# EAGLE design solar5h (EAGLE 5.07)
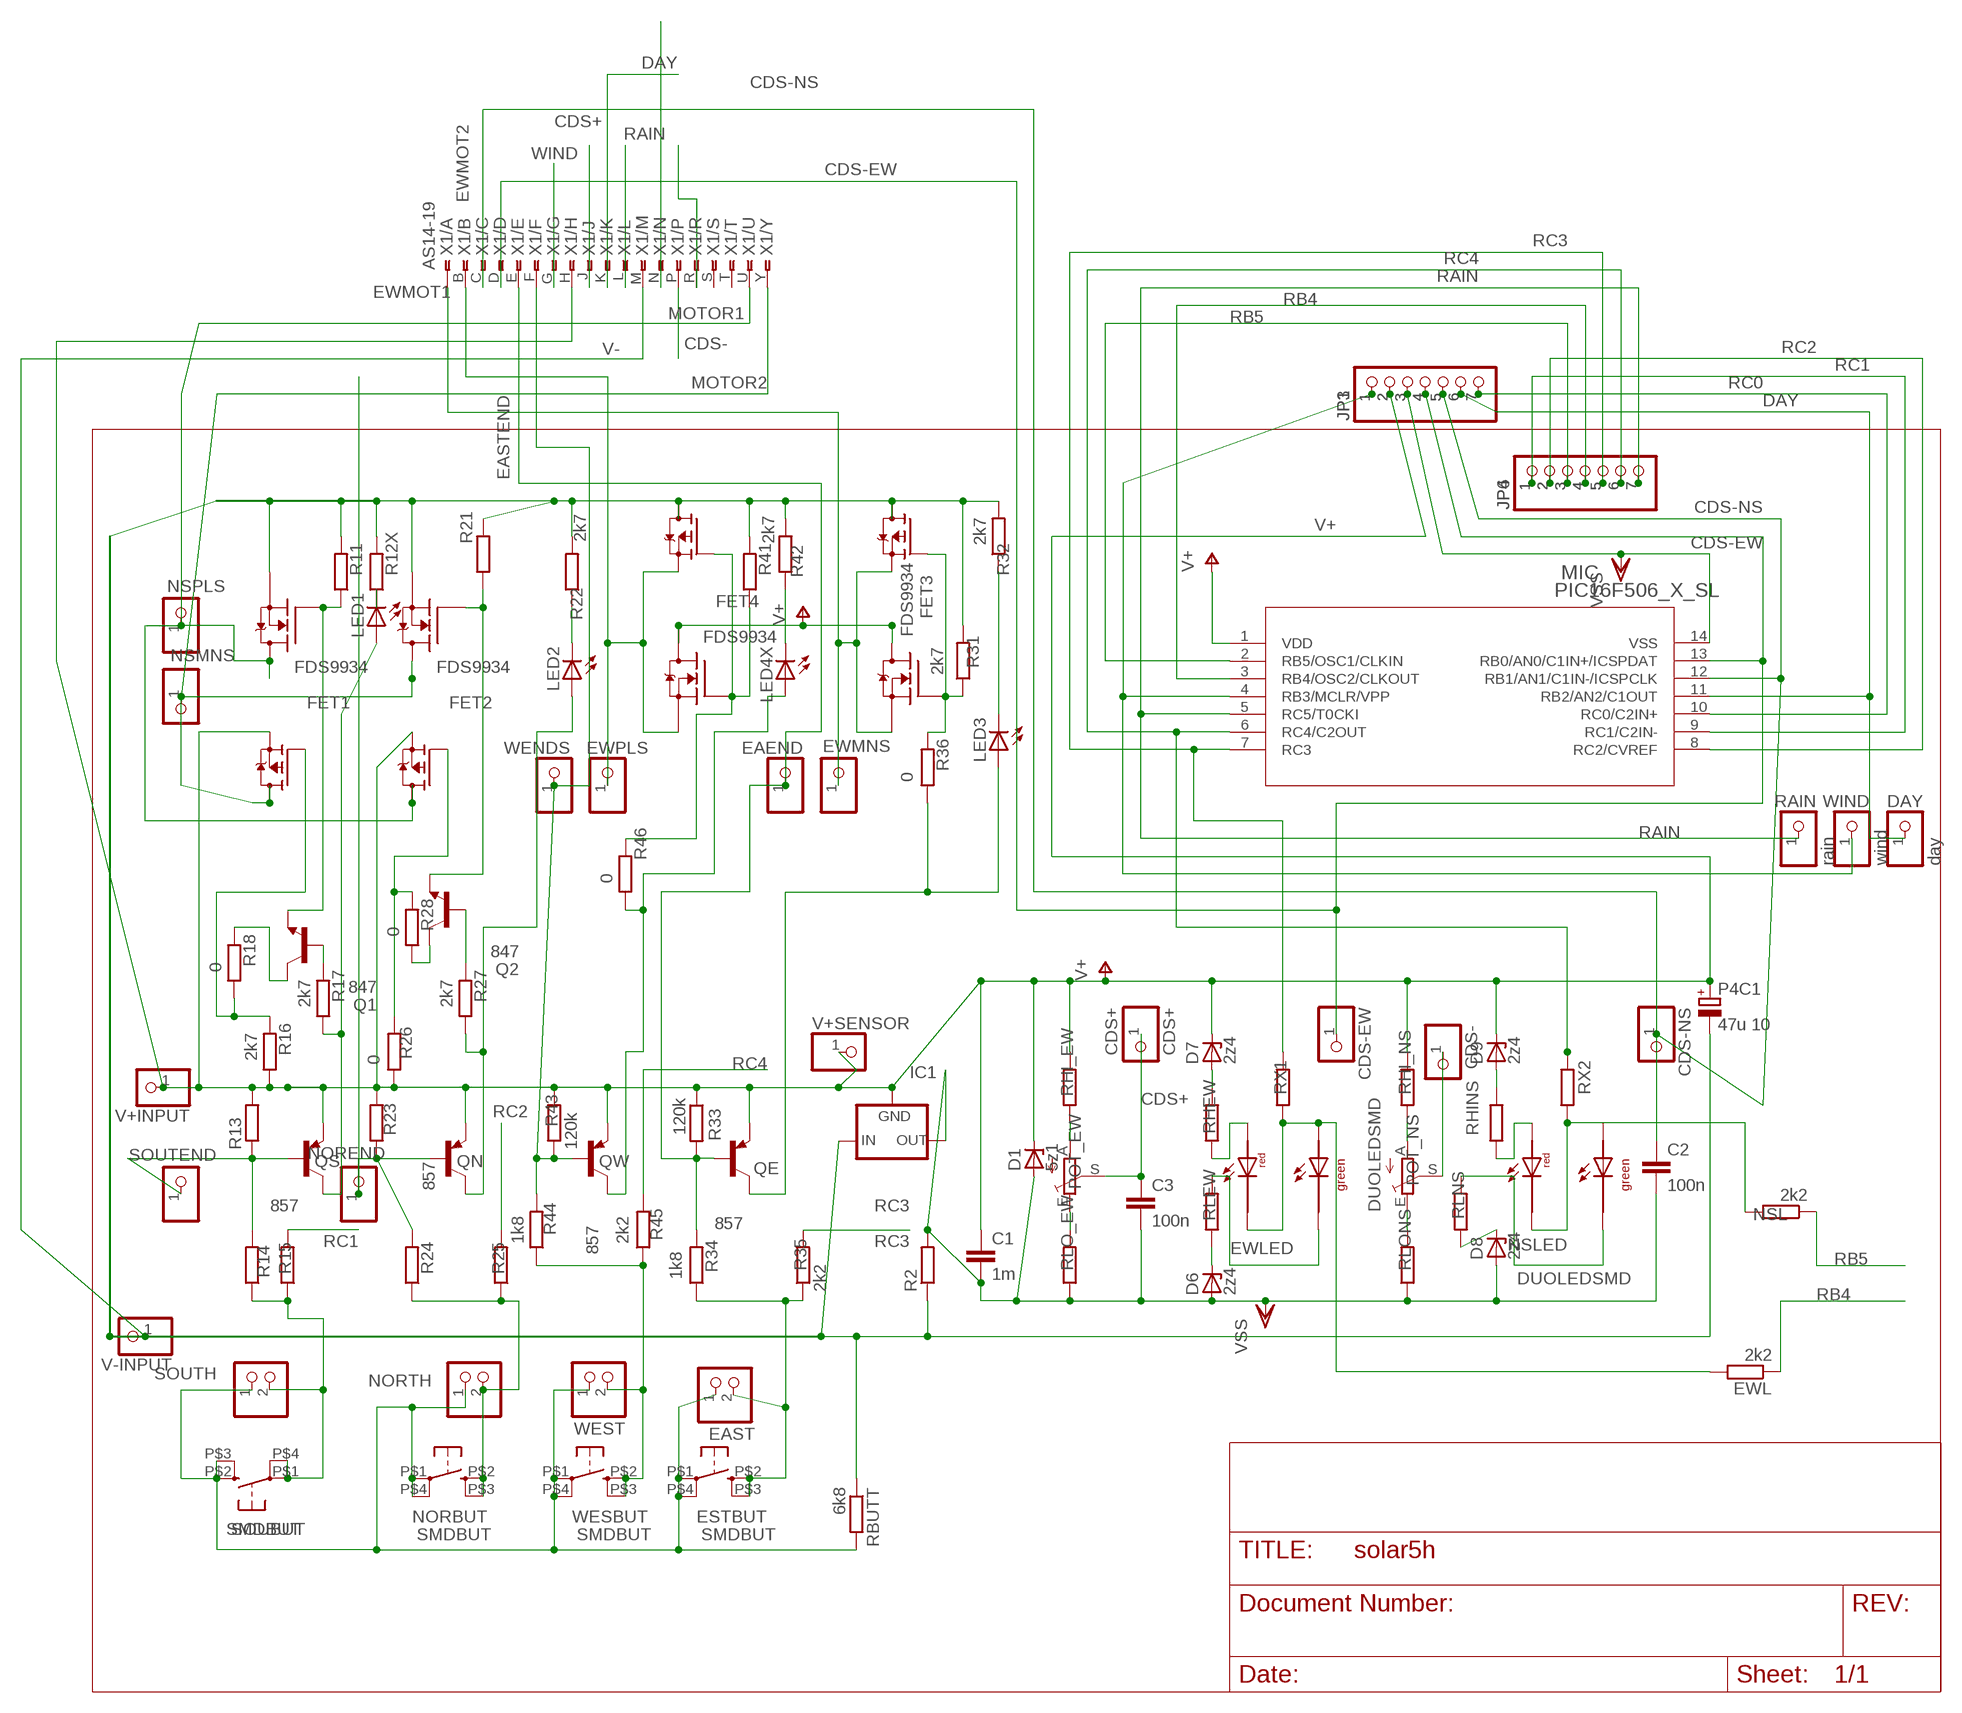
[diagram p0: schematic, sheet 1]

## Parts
C1  1m  C-EUC1206  [C1206]
C2  100n  C-EUC1206  [C1206]
C3  100n  C-EUC1206  [C1206]
CDS+  CDS+  PINHD-1X1INCH  [1X01]
CDS-  PINHD-1X1INCH  [1X01]
CDS-EW  PINHD-1X1INCH  [1X01]
CDS-NS  PINHD-1X1INCH  [1X01]
D1  5z1  ZENER-DIODESOD80C  [SOD80C]
D6  2z4  ZENER-DIODESOD80C  [SOD80C]
D7  2z4  ZENER-DIODESOD80C  [SOD80C]
D8  2z4  ZENER-DIODESOD80C  [SOD80C]
D9  2z4  ZENER-DIODESOD80C  [SOD80C]
DAY  day  PINHD-1X1INCH  [1X01]
EAEND  PINHD-1X1INCH  [1X01]
EAST  PINHD-1X2STR  [1X02]
ESTBUT  SMDBUT  [SMD10/5]
EWL  2k2  R-EU_R0805  [R0805]
EWLED  DUOLEDSMD  [DUOLEDSMD]
EWMNS  PINHD-1X10MM6  [1X01M]
EWPLS  PINHD-1X10MM6  [1X01M]
FET1  FDS9934  [SO-8]
FET2  FDS9934  [SO-8]
FET3  FDS9934  [SO-8]
FET4  FDS9934  [SO-8]
IC1  79LXX  [79LXX]
JP1  PINHD-1X7  [1X07]
JP3  PINHD-1X7  [1X07]
JP4  PINHD-1X7  [1X07]
JP6  PINHD-1X7  [1X07]
LED1  LEDCHIPLED_1206  [CHIPLED_1206]
LED2  LEDCHIPLED_1206  [CHIPLED_1206]
LED3  LEDCHIPLED_1206  [CHIPLED_1206]
LED4X  LEDCHIPLED_1206  [CHIPLED_1206]
MIC  PIC16F506_X_SL  [SOIC14_N_MC]
NORBUT  SMDBUT  [SMD10/5]
NOREND  PINHD-1X1INCH  [1X01]
NORTH  PINHD-1X2STR  [1X02]
NSL  2k2  R-EU_R0805  [R0805]
NSLED  DUOLEDSMD  [DUOLEDSMD]
NSMNS  PINHD-1X1INCH  [1X01]
NSPLS  PINHD-1X10MM6  [1X01M]
P4C1  47u 10  CPOL-EUE5-8.5  [E5-8,5]
POT_EW  TRIM_EU-CA6V  [CA6V]
POT_NS  TRIM_EU-CA6V  [CA6V]
Q1  847  BC847ASMD  [SOT23]
Q2  847  BC847ASMD  [SOT23]
QE  857  BC327SMD  [SOT23-BEC]
QN  857  BC327SMD  [SOT23-BEC]
QS  857  BC327SMD  [SOT23-BEC]
QW  857  BC327SMD  [SOT23-BEC]
R2  R-EU_R0805  [R0805]
R11  R-EU_R1206  [R1206]
R12X  R-EU_R0805  [R0805]
R13  R-EU_R0805  [R0805]
R14  R-EU_R1206  [R1206]
R15  R-EU_R0805  [R0805]
R16  2k7  R-EU_R0805  [R0805]
R17  2k7  R-EU_R0805  [R0805]
R18  0  R-EU_R0805  [R0805]
R21  R-EU_R0805  [R0805]
R22  2k7  R-EU_R0805  [R0805]
R23  R-EU_R0805  [R0805]
R24  R-EU_R1206  [R1206]
R25  R-EU_R0805  [R0805]
R26  0  R-EU_R0805  [R0805]
R27  2k7  R-EU_R0805  [R0805]
R28  0  R-EU_R0805  [R0805]
R31  2k7  R-EU_R0805  [R0805]
R32  2k7  R-EU_R0805  [R0805]
R33  120k  R-EU_R0805  [R0805]
R34  1k8  R-EU_R0805  [R0805]
R35  2k2  R-EU_R0805  [R0805]
R36  0  R-EU_R0805  [R0805]
R41  R-EU_R0805  [R0805]
R42  2k7  R-EU_R0805  [R0805]
R43  120k  R-EU_R0805  [R0805]
R44  1k8  R-EU_R0805  [R0805]
R45  2k2  R-EU_R0805  [R0805]
R46  0  R-EU_R0805  [R0805]
RAIN  rain  PINHD-1X1INCH  [1X01]
RBUTT  6k8  R-EU_R0805  [R0805]
RHEW  R-EU_R1206  [R1206]
RHI_EW  R-EU_R1206  [R1206]
RHI_NS  R-EU_R1206  [R1206]
RHINS  R-EU_R1206  [R1206]
RLEW  R-EU_R1206  [R1206]
RLNS  R-EU_R1206  [R1206]
RLO_EW  R-EU_R1206  [R1206]
RLONS  R-EU_R0805  [R0805]
RX1  R-EU_R1206  [R1206]
RX2  R-EU_R0805  [R0805]
SOUBUT  SMDBUT  [SMD10/5]
SOUTEND  PINHD-1X1INCH  [1X01]
SOUTH  PINHD-1X2STR  [1X02]
V+INPUT  PINHD-1X1INCH  [1X01]
V+SENSOR  PINHD-1X10MM6  [1X01M]
V-INPUT  PINHD-1X10MM6  [1X01M]
WENDS  PINHD-1X1INCH  [1X01]
WESBUT  SMDBUT  [SMD10/5]
WEST  PINHD-1X2STR  [1X02]
WIND  wind  PINHD-1X1INCH  [1X01]
X1  AS14-19  AS14-19OLIVE  [Y28M-19TK]

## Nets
CDS+: C3.1 CDS+.1 POT_EW.S X1.J
CDS-: CDS-.1 POT_NS.S X1.P
CDS-EW: CDS-EW.1 JP1.4 JP3.4 MIC.13(RB0/AN0/C1IN+/ICSPDAT) X1.D
CDS-NS: C2.1 CDS-NS.1 JP1.5 JP3.5 MIC.12(RB1/AN1/C1IN-/ICSPCLK) X1.C
DAY: DAY.1 JP1.6 JP3.6 MIC.11(RB2/AN2/C1OUT) X1.K
EASTEND: EAEND.1 QE.B R33.2 R34.2 X1.E
EWMOT1: EWMNS.1 FET3.1(Q1S) FET3.3(Q2S) X1.A
EWMOT2: EWPLS.1 FET4.1(Q1S) FET4.3(Q2S) X1.B
F1NG: FET1.2(Q1G) Q1.2(E) R11.1
F1PG: FET1.4(Q2G) R16.2 R18.1
F2NG: FET2.2(Q1G) Q2.2(E) R21.1
F2PG: FET2.4(Q2G) R26.2 R28.2
MOTOR1: FET1.7(Q1D2) FET1.8(Q1D1) FET2.5(Q2D2) FET2.6(Q2D) NSPLS.1 X1.U
MOTOR2: FET1.5(Q2D2) FET1.6(Q2D) FET2.7(Q1D2) FET2.8(Q1D1) NSMNS.1 X1.Y
N$1: POT_NS.E RLONS.2
N$2: LED1.A QS.C R17.1
N$3: LED2.A QN.C R27.1
N$5: LED1.C R12X.1
N$6: EWL.2 EWLED.AGRN EWLED.CRED RX1.1
N$8: LED2.C R22.1
N$9: R14.1 R15.1 SOUBUT.P$1(P) SOUBUT.P$4(P1) SOUTH.2
N$10: LED4X.A QW.C R46.1
N$11: EAST.2 ESTBUT.P$2(S) ESTBUT.P$3(S1) R34.1 R35.1
N$12: Q2.3(C) R28.1
N$14: D7.A RHEW.2
N$15: LED4X.C R42.1
N$17: NORBUT.P$2(S) NORBUT.P$3(S1) NORTH.2 R24.1 R25.1
N$18: POT_NS.A RHI_NS.1
N$19: Q1.1(B) R17.2
N$20: Q1.3(C) R18.2
N$21: POT_EW.E RLO_EW.2
N$22: POT_EW.A RHI_EW.1
N$23: Q2.1(B) R27.2
N$25: EWLED.ARED RHEW.1
N$27: D6.C RLEW.1
N$28: EWLED.CGRN RLEW.2
N$29: EAST.1 ESTBUT.P$1(P) ESTBUT.P$4(P1) NORBUT.P$1(P) NORBUT.P$4(P1) NORTH.1 RBUTT.2 SOUBUT.P$2(S) SOUBUT.P$3(S1) SOUTH.1 WESBUT.P$1(P) WESBUT.P$4(P1) WEST.1
N$30: NSL.2 NSLED.AGRN NSLED.CRED RX2.1
N$37: LED3.A QE.C R36.1
N$39: R44.1 R45.1 WESBUT.P$2(S) WESBUT.P$3(S1) WEST.2
N$41: D9.A RHINS.2
N$42: NSLED.ARED RHINS.1
N$43: D8.C RLNS.1
N$44: NSLED.CGRN RLNS.2
N$54: FET4.2(Q1G) FET4.4(Q2G) R41.1 R46.2
N$55: FET3.2(Q1G) FET3.4(Q2G) R31.1 R36.2
N$56: LED3.C R32.1
NOREND: NOREND.1 QN.B R23.1 R24.2 X1.N
RAIN: JP4.7 JP6.7 MIC.5(RC5/T0CKI) RAIN.1 X1.L
RB4: EWL.1 JP4.4 JP6.4 MIC.3(RB4/OSC2/CLKOUT)
RB5: JP4.3 JP6.3 MIC.2(RB5/OSC1/CLKIN) NSL.1
RC0: JP1.7 JP3.7 MIC.10(RC0/C2IN+)
RC1: JP4.1 JP6.1 MIC.9(RC1/C2IN-) R15.2
RC2: JP4.2 JP6.2 MIC.8(RC2/CVREF) R25.2
RC3: JP4.5 JP6.5 MIC.7(RC3) R35.2 RX1.2
RC4: JP4.6 JP6.6 MIC.6(RC4/C2OUT) R45.2 RX2.2
SOU_END: QS.B R13.1 R14.2 SOUTEND.1 X1.R
V+: C1.1 D1.C D7.C D9.C FET1.3(Q2S) FET2.3(Q2S) FET3.7(Q1D2) FET3.8(Q1D1) FET4.7(Q1D2) FET4.8(Q1D1) IC1.GND JP1.2 JP3.2 MIC.1(VDD) P4C1.+ QE.E QN.E QS.E QW.E R13.2 R16.1 R23.2 R26.1 R33.1 R43.2 RHI_EW.2 RHI_NS.2 V+INPUT.1 V+SENSOR.1 X1.H
V-: FET1.1(Q1S) FET2.1(Q1S) FET3.5(Q2D2) FET3.6(Q2D) FET4.5(Q2D2) FET4.6(Q2D) IC1.IN P4C1.- R2.1 R11.2 R12X.2 R21.2 R22.2 R31.2 R32.2 R41.2 R42.2 RBUTT.1 V-INPUT.1 X1.M
VSS: C1.2 C2.2 C3.2 D1.A D6.A D8.A IC1.OUT JP1.3 JP3.3 MIC.14(VSS) R2.2 RLO_EW.1 RLONS.1
WESTEND: QW.B R43.1 R44.2 WENDS.1 X1.F
WIND: JP1.1 JP3.1 MIC.4(RB3/MCLR/VPP) WIND.1 X1.G
Unconnected: X1.S X1.T

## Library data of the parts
C1-C3 = rcl-2:C-EU: CAPACITOR, European symbol
CDS+ CDS- CDS-EW CDS-NS DAY EAEND EWMNS EWPLS NOREND NSMNS NSPLS RAIN SOUTEND V+INPUT V+SENSOR V-INPUT WENDS WIND = pinhead(2):PINHD-1X1: PIN HEADER
D1 D6-D9 = diode-1:ZENER-DIODE: Z-Diode
EAST NORTH SOUTH WEST = pinhead:PINHD-1X2: PIN HEADER
ESTBUT NORBUT SOUBUT WESBUT = switch-omron:SMDBUT
EWL NSL R2 R11 R12X R13-R18 R21-R28 R31-R36 R41-R46 RBUTT RHEW RHI_EW RHI_NS RHINS RLEW RLNS RLO_EW RLONS RX1 RX2 = rcl-2:R-EU_: RESISTOR, European symbol
EWLED NSLED = led:DUOLEDSMD
FET1-FET4 = transistor-fet:FDS9934
IC1 = v-reg:79LXX: VOLTAGE REGULATOR
JP1 JP3 JP4 JP6 = pinhead:PINHD-1X7: PIN HEADER
LED1-LED3 LED4X = led:LED: LED
MIC = pic16f506mc:PIC16F506_X_SL
P4C1 = rcl:CPOL-EU: POLARIZED CAPACITOR, European symbol
POT_EW POT_NS = pot:TRIM_EU-: POTENTIOMETER
Q1 Q2 = transistor-npn:BC847*: NPN Transistor
QE QN QS QW = transistor-pnp:BC327*: PNP Transistror
X1 = con-deutsch:AS14-19: DEUTSCH Connector

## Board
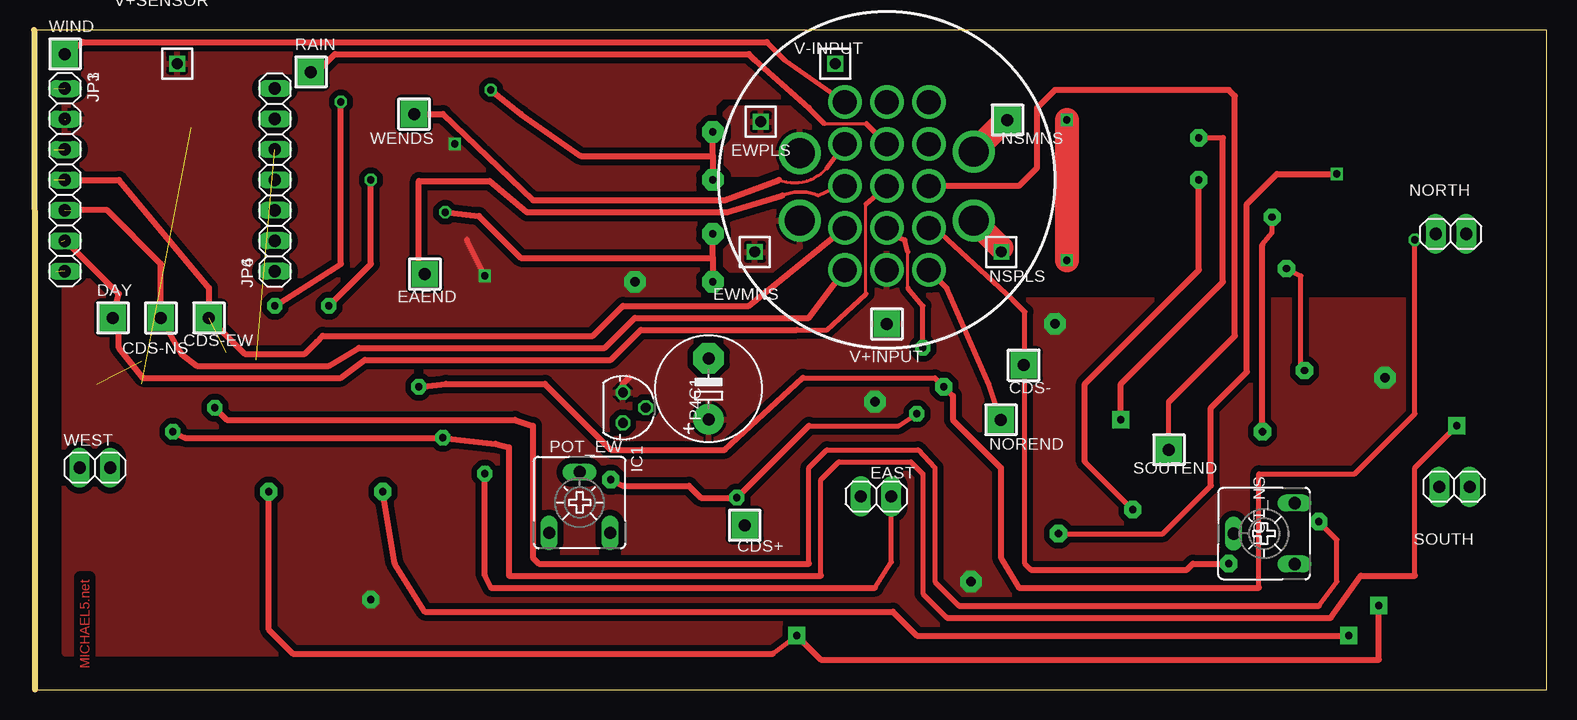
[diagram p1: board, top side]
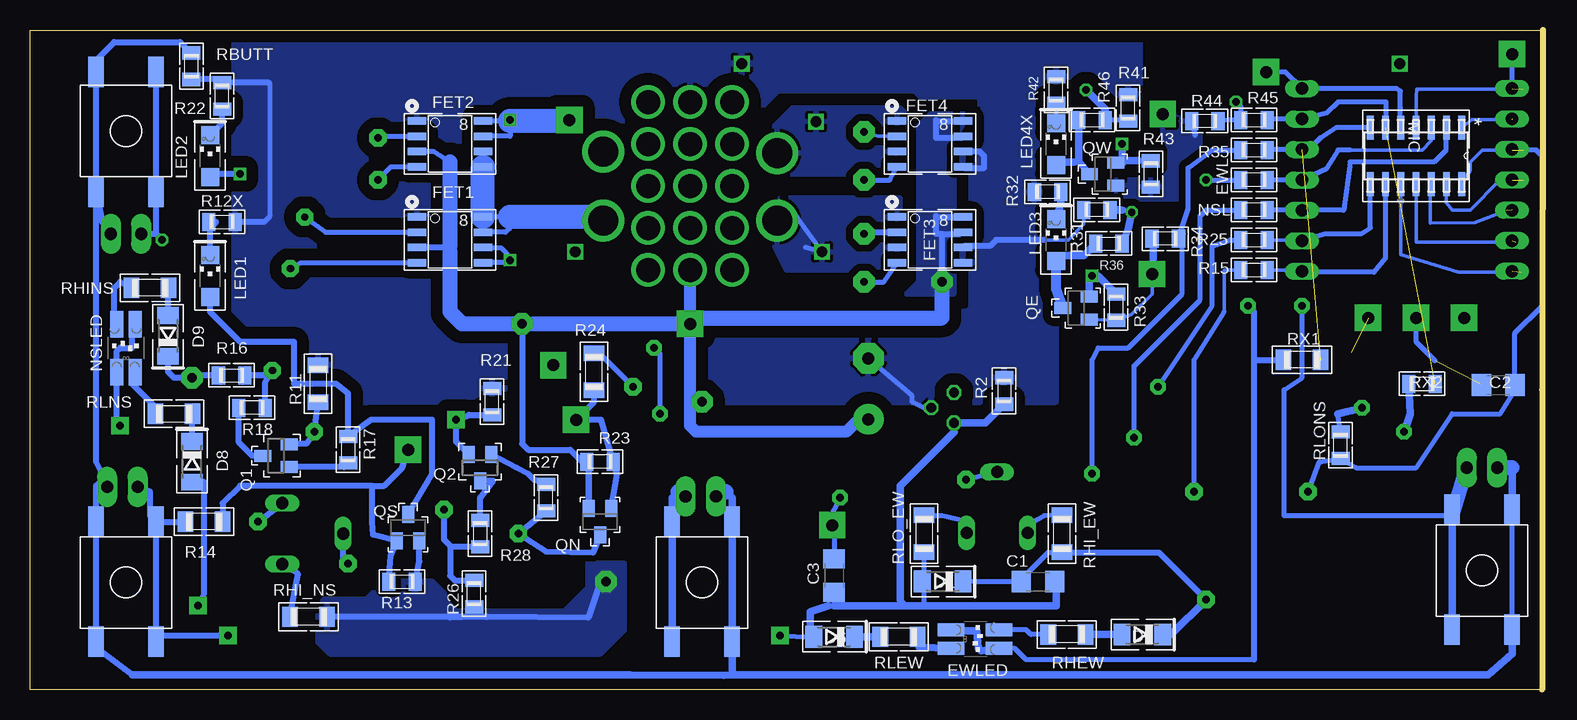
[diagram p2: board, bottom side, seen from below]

Size 126.07 x 55 mm. Coordinates in mm from the lower left corner, seen from the top.
Outline: 0.07,0 126.07,0 126.07,55 0,55 0.07,25 0.07,0
Copper layers (1*16): Top 0.035mm / dielectric 1.5mm / Bottom 0.035mm
Design rules "default *": minimum track width 40mil, minimum drill 30mil, track to track 8mil, track to pad 8mil, pad to pad 8mil, via to via 8mil, smd to smd 8mil, copper to edge 40mil, drill to drill 8mil, minimum pad ring 8mil, minimum via ring 8mil, stop-mask expansion 4mil, vias tented up to drill 0mil, thermal gap 10mil

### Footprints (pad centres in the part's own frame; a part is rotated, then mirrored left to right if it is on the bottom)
C1206 = smd 1.6 x 1.8: 1 -1.4,0; 2 1.4,0
1X01 = drill 1 pad 2.184 square: 1 0,0
SOD80C = smd 1.4 x 1.8: A 1.7,0; C -1.7,0
1X02 = drill 1.016 pad 1.676 long: 1 -1.27,0; 2 1.27,0
SMD10/5 = smd 1.27 x 2.54: P$1 -2.5,0; P$2 2.5,0; P$3 2.5,10; P$4 -2.5,10
R0805 = smd 1.1 x 1.5: 1 -1.1,0; 2 1.1,0
DUOLEDSMD = smd 1.067 x 2.184: AGRN 0.77,1.95; ARED -0.77,1.95; CGRN 0.77,-2.05; CRED -0.77,-2.05
1X01M = drill 0.914 square: 1 0,0
SO-8 = smd 1.524 x 0.61: 1 -2.743,1.905; 2 -2.743,0.635; 3 -2.743,-0.635; 4 -2.743,-1.905; 5 2.743,-1.905; 6 2.743,-0.635; 7 2.743,0.635; 8 2.743,1.905
79LXX = drill 0.813 octagon: GND -1.27,0; IN 0,1.905; OUT 1.27,0
1X07 = drill 1.016 long: 1 -7.62,0; 2 -5.08,0; 3 -2.54,0; 4 0,0; 5 2.54,0; 6 5.08,0; 7 7.62,0
CHIPLED_1206 = smd 1.5 x 1.5: A 0,-1.75; C 0,1.75
SOIC14_N_MC = smd 1.981 x 0.559: 1 -2.362,3.81; 2 -2.362,2.54; 3 -2.362,1.27; 4 -2.362,0; 5 -2.362,-1.27; 6 -2.362,-2.54; 7 -2.362,-3.81; 8 2.362,-3.81; 9 2.362,-2.54; 10 2.362,-1.27; 11 2.362,0; 12 2.362,1.27; 13 2.362,2.54; 14 2.362,3.81
E5-8,5 = drill 1 pad 2.54 round: + -2.54,0 | drill 1 pad 2.54 octagon: - 2.54,0
CA6V = drill 1.016 long: A -2.54,-2.54; E 2.54,-2.54; S 0,2.54
SOT23 = smd 1 x 1.4: 1 -0.95,-1.1; 2 0.95,-1.1; 3 0,1.1
SOT23-BEC = smd 1 x 1.4: B -0.95,-1.1; C 0,1.1; E 0.95,-1.1
R1206 = smd 1.3 x 1.7: 1 -1.55,0; 2 1.55,0
Y28M-19TK = drill 2.5 pad 3.5 round: A -7.25,-2.875; B -7.25,2.75; U 7.25,-2.875; Y 7.25,2.875 | drill 2 pad 2.54 round: C -3.5,-7; D -3.5,-3.5; E -3.5,0; F -3.5,3.5; G -3.5,7; H 0,-7; J 0,-3.5; K 0,0; L 0,3.5; M 0,7; N 3.5,-7; P 3.5,-3.5; R 3.5,0; S 3.5,3.5; T 3.5,7

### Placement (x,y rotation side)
C1  42.07,9 0 bottom
C2  3.72,25.39 0 bottom
C3  59.07,9.5 270 bottom
CDS+  59.22,13.7 0 top
CDS-  82.47,27.05 90 top
CDS-EW  14.57,31 0 top
CDS-NS  10.57,31 90 top
D1  50.02,9.02 180 bottom
D6  59.07,4.4 180 bottom
D7  33.37,4.6 180 bottom
D8  112.57,19 270 bottom
D9  114.57,29.5 90 bottom
DAY  6.57,31 0 top
EAEND  32.57,34.65 90 top
EAST  70.17,16.1 0 top
ESTBUT  70.07,14 180 bottom
EWL  24.07,42.5 180 bottom
EWLED  47.27,4.2 270 bottom
EWMNS  60.07,36.5 90 top
EWPLS  60.57,47.35 90 top
FET1  91.07,37.5 0 bottom
FET2  91.07,45.5 0 bottom
FET3  51.07,37.5 0 bottom
FET4  51.07,45.5 0 bottom
IC1  49.07,23.5 270 top
JP1  2.57,42.5 270 top
JP3  2.57,42.5 270 top
JP4  20.07,42.5 90 top
JP6  20.07,42.5 90 top
LED1  111.07,34.5 0 bottom
LED2  111.07,44.5 0 bottom
LED3  40.57,37.5 0 bottom
LED4X  40.57,45.5 0 bottom
MIC  10.57,44.5 270 bottom
NORBUT  118.07,41.5 0 bottom
NOREND  80.57,22.5 0 top
NORTH  118.07,38 180 top
NSL  24.07,40 180 bottom
NSLED  118.07,28.5 0 bottom
NSMNS  81.12,47.5 0 top
NSPLS  80.62,36.5 0 top
P4C1  56.21,25.08 90 top
POT_EW  45.47,15.6 0 top
POT_NS  102.51,13.01 90 top
Q1  105.57,19.5 90 bottom
Q2  88.57,18.5 180 bottom
QE  38.9,31.81 90 bottom
QN  78.57,14 180 bottom
QS  94.57,13.5 0 bottom
QW  36.68,42.98 90 bottom
R2  44.89,24.89 270 bottom
R11  102.07,25.5 90 bottom
R12X  110.07,39 0 bottom
R13  95.07,9 0 bottom
R14  111.57,14 0 bottom
R15  24.07,35 0 bottom
R16  109.27,26.2 0 bottom
R17  99.57,20 270 bottom
R18  107.57,23.5 180 bottom
R21  87.57,24 90 bottom
R22  110.07,49.5 90 bottom
R23  78.57,19 180 bottom
R24  79.07,26.5 270 bottom
R25  24.07,37.5 0 bottom
R26  89.07,8 90 bottom
R27  83.07,16 90 bottom
R28  88.57,13 270 bottom
R31  37.17,40 180 bottom
R32  41.27,41.5 180 bottom
R33  35.57,31.89 270 bottom
R34  31.47,37.6 180 bottom
R35  24.07,45 0 bottom
R36  36.17,37.2 0 bottom
R41  34.57,48.5 90 bottom
R42  40.57,50 90 bottom
R43  32.66,42.99 90 bottom
R44  28.17,47.4 180 bottom
R45  24.07,47.5 0 bottom
R46  37.57,47.5 0 bottom
RAIN  23.07,51.5 0 top
RBUTT  112.62,51.98 90 bottom
RHEW  39.67,4.6 0 bottom
RHI_EW  40.07,13 270 bottom
RHI_NS  102.86,6.06 0 bottom
RHINS  116.07,33.5 0 bottom
RLEW  53.67,4.4 0 bottom
RLNS  114.07,23 180 bottom
RLO_EW  51.57,13 90 bottom
RLONS  16.86,20.37 90 bottom
RX1  20.07,27.5 0 bottom
RX2  10.07,25.5 0 bottom
SOUBUT  118.07,14 180 bottom
SOUTEND  94.57,20 0 top
SOUTH  118.37,16.9 180 top
V+INPUT  71.07,30.5 90 top
V+SENSOR  11.92,52.2 90 top
V-INPUT  66.77,52.2 90 top
WENDS  31.67,48 90 top
WESBUT  5.07,15 180 bottom
WEST  5.07,18.5 0 top
WIND  2.57,53 0 top
X1  71.07,42 0 top

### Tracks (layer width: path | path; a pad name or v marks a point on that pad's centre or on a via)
CDS+  (via drill 0.6 pad 1.27, 0.6 pad 1.42)
  Top 0.254: 72.82,33.5 72.82,36.5
  Top 0.406: X1.J 71.07,38 72.57,37.5 72.82,36.5 | v73.57,23 72.07,22 64.57,22 | v74.07,28.5 74.07,32 72.82,33.5
  Top 0.5: 64.57,22 v58.57,16 55.57,16 54.57,17 49.07,17 v48.07,17.5
  Bottom 0.406: v73.57,23 73.57,28 v74.07,28.5 | v58.57,16 59.57,14.05 CDS+.1 59.07,13.55 C3.1 | v48.07,17.5 46.11,18 POT_EW.S
CDS-  (via drill 0.6 pad 1.42)
  Top 0.406: X1.P 75.07,38.5 81.57,32.5 82.57,31.5 82.57,27.15 | 83.07,10 82.57,10.5 82.57,27.15 | 82.57,27.15 CDS-.1
  Top 0.5: 83.07,10 96.07,10 96.57,10.5 v99.57,10.5
  Bottom 0.5: POT_NS.S 99.97,10.9 v99.57,10.5
CDS-EW  (2 unrouted)
  Top 0.5: JP3.4 7.07,42.5 14.57,33.5 CDS-EW.1 17.57,28 22.57,28 23.56,28.99 24.06,29.51 24.07,29.5 46.57,29.5 49.07,32 59.57,32 X1.D
  Bottom 0.305: MIC.13 8.07,40.6 7.57,40 6.07,40 3.61,42.46 1.64,42.46
CDS-NS  (2 unrouted)
  Top 0.5: X1.C 64.57,31 50.07,31 47.57,28.5 27.07,28.5 24.57,27 13.57,27 12.27,28 CDS-NS.1 10.57,35.5 6.11,39.96 JP3.5
  Bottom 0.305: MIC.12 9.37,41.31 9.37,38.9 5.69,38.92 3.04,39.92
  Bottom 0.406: 8.97,27.4 10.57,29 CDS-NS.1 | C2.1 5.22,25.5
DAY  (1 unrouted)
  Top 0.254: 69.32,33 69.32,40.5
  Top 0.406: 69.32,40.5 X1.K | 63.57,30 66.07,30 69.32,33
  Top 0.5: JP3.6 2.99,37 3.07,37 7.07,33 DAY.1 7.07,30.5 7.07,28.5 9.07,26 25.57,26 27.57,27.5 48.07,27.5 50.57,30 63.57,30
  Bottom 0.305: MIC.11 10.57,37.3 2.26,37.3
EASTEND
  Top 0.305: X1.E 67.07,42 65.37,41.2 arc45 62.37,41.2
  Top 0.5: 62.37,41.2 57.77,39.8 41.07,39.8 37.97,42.4 32.07,42.4 32.07,35.5 EAEND.1
  Bottom 0.305: QE.B 37.14,30.86 R33.2 34.28,31.29 32.57,33 EAEND.1 | 32.47,37.4 R34.2
  Bottom 0.61: EAEND.1 32.47,36.2 32.47,37.4
EWMOT1
  Bottom 0.406: 61.44,36.87 EWMNS.1 62.16,39.41
  pour Bottom (isolate 0.61): 53.57,41 63.57,41 64.07,39.5 64.07,37 63.07,35 54.07,35 53.57,36.5
  pour Top (isolate 0.61): 56.07,39 63.57,41 64.07,39.5 64.07,37 63.07,35 56.57,35 56.07,36.5
EWMOT2
  Bottom 0.406: FET4.1 53.91,47.5
  pour Bottom (isolate 0.61): 54.07,44.5 53.07,48 53.57,48.5 62.57,48.5 64.07,47 64.07,45 63.07,43 54.57,43
  pour Top (isolate 0.61): 57.57,43 57.57,48 58.07,48.5 63.07,48.5 64.57,47 64.57,45 63.57,43
F1NG  (via drill 0.6 pad 1.42)
  Top 0.406: 102.37,37.1 103.17,38.1 v103.17,39.4
  Top 0.5: v102.37,21.5 102.37,37.1
  Bottom 0.406: FET1.2 101.43,38.13 v103.17,39.4
  Bottom 0.5: v102.37,21.5 R11.1 | v102.37,21.5 101.97,21.4 | v102.37,21.5 103.07,20.5 104.42,20.5 Q1.2
F1PG  (via drill 0.6 pad 1.42)
  Top 0.406: v105.87,26.6 105.57,27 105.57,34.5 v104.37,35.1
  Bottom 0.406: FET1.4 103.47,35.59 v104.37,35.1
  Bottom 0.5: R16.2 106.27,26.2 v105.87,26.6 106.47,25.6 R18.1
F2NG  (via drill 0.6 pad 1.42)
  Top 0.406: 99.07,46 v97.07,46
  Top 0.5: 99.07,46 99.07,34 90.57,25.5 v90.57,22.5
  Bottom 0.406: FET2.2 97.07,46.13 v97.07,46
  Bottom 0.5: Q2.2 90.57,20.65 v90.57,22.5 89.47,22.9 R21.1
F2PG  (via drill 0.6 pad 1.42)
  Top 0.406: v91.57,15 87.57,19
  Top 0.5: v97.07,42.5 97.07,35 87.57,25.5 87.57,19
  Bottom 0.406: FET2.4 95.97,43.59 v97.07,42.5
  Bottom 0.5: R28.2 90.97,11.9 91.32,12.25 | 91.32,12.25 91.57,12.5 v91.57,15 | R26.2 90.67,9.1 91.07,9.5 91.07,12 91.32,12.25
MOTOR1
  Top 0.406: 80.62,36.83 NSPLS.1
  Top 2: X1.U 80.62,36.83
  Bottom 0.406: FET2.5 FET2.6 | FET1.8 86.07,39.41 86.07,38.5 86.43,38.13 FET1.7 | X1.U 78.32,39.41
  Bottom 2: FET1.8 FET2.5 | 78.32,39.41 86.07,39.41
MOTOR2  (via drill 0.6)
  Top 0.406: 80.94,47.5 NSMNS.1
  Top 2: X1.Y 80.94,47.5 | v86.07,47.5 v86.07,35.8
  Bottom 0.406: 86.07,47.41 FET2.8 | v86.07,35.8 85.97,36 86.77,36.8 88.07,36.8 88.23,36.8 | v86.07,35.8 86.07,36 86.47,35.59 FET1.5 | v86.07,35.8 86.07,35.59 | FET2.7 86.07,46.13 86.07,47.41 | 86.07,47.41 v86.07,47.5 | NSMNS.1 81.21,47.41
  Bottom 0.5: FET1.6 88.13,36.87 88.07,36.8
  Bottom 2: 81.21,47.41 86.07,47.41
N$1  (via drill 0.6 pad 1.27, 0.6 pad 1.42)
  Top 0.406: 64.57,10.5 64.57,18.5 66.07,20 73.67,20 75.07,18.5 75.07,9 77.07,7 | 107.07,7 108.57,9 108.57,12.5 v107.07,14
  Top 0.5: v15.07,23.5 16.07,22.5 40.07,22.5 41.57,22 41.57,11 42.07,10.5 64.57,10.5 | 77.07,7 107.07,7
  Bottom 0.406: RLONS.2 17.1,22.97
  Bottom 0.5: v107.07,14 105.09,15.5 POT_NS.E
  Bottom 0.61: 17.1,22.97 v15.07,23.5
N$2
  Bottom 0.5: QS.C 92.57,18 92.57,22.5 97.67,22.5 R17.1 99.57,24.7 100.57,25.5 104.07,25.5 104.07,29 108.57,29 111.07,31.5 LED1.A
N$3  (via drill 0.6, 0.6 pad 1.42)
  Top 0.406: 98.07,17 94.07,13 v85.37,13
  Top 0.5: v108.57,43 103.57,43 101.07,40.5 101.07,26.5 98.07,23.5 98.07,17
  Bottom 0.5: v108.57,43 110.82,43 LED2.A | QN.C 79.17,11.4 83.07,11.5 v85.37,13 R27.1
N$5
  Bottom 0.5: R12X.1 110.57,39 111.07,38.5 LED1.C
N$6  (via drill 0.6, 0.6 pad 1.27)
  Top 0.5: v24.57,32 28.07,35.5 v28.07,42.5
  Bottom 0.406: EWLED.AGRN 44,3.43 43.07,2.5 24.07,2.5 | v28.07,42.5 EWL.2
  Bottom 0.5: 24.07,2.5 24.07,27.5 | 24.07,27.5 24.07,31.5 v24.57,32 | 24.07,27.5 RX1.1
  Bottom 0.61: EWLED.AGRN 46.8,3.23 47.07,3.5 47.17,4.9 48.95,4.9 EWLED.CRED
N$8
  Bottom 0.5: R22.1 110.07,47.25 LED2.C
N$9  (via drill 0.6 pad 1.42)
  Top 0.5: v109.57,4.5 73.57,4.5 71.57,6.5 32.57,6.5 30.07,10.5 v29.07,16.5
  Bottom 0.305: 26.57,31.5 26.57,35 R15.1
  Bottom 0.406: 26.57,31.5 29.07,27.5 v29.07,16.5
  Bottom 0.5: SOUBUT.P$1 SOUBUT.P$4 115.07,4.5 v109.57,4.5 | SOUBUT.P$1 116.07,14.5 116.07,16.5 SOUTH.2 | SOUBUT.P$1 R14.1
N$10
  Bottom 0.305: 38.67,44.4 39.07,44 | 40.32,44 LED4X.A
  Bottom 0.61: 39.07,44 40.32,44 | QW.C 38.67,44.06 38.67,44.4 R46.1
N$11  (via drill 0.6 pad 1.27)
  Top 0.406: EAST.2 71.44,10.63 70.07,8.5
  Top 0.5: 70.07,8.5 38.07,8.5 37.57,9.5 v37.57,18
  Bottom 0.406: R35.1 27.57,45 29.57,43.5 29.57,40.1 R34.1 | 30.07,38.5 30.07,38 30.07,33 34.57,28.5 37.07,28.5 37.57,27.5 v37.57,18
  Bottom 0.61: ESTBUT.P$3 ESTBUT.P$2 72.57,16 72.07,16.5 | R34.1 30.37,37.7 30.07,38
  Bottom 1.27: EAST.2 72.07,16.5
N$12
  Bottom 0.5: Q2.3 87.47,17.4 88.57,16 R28.1
N$14
  Bottom 0.61: D7.A RHEW.2
N$15
  Bottom 0.305: LED4X.C R42.1
N$17  (via drill 0.6, 0.6 pad 1.27, 0.6 pad 1.42)
  Top 0.406: 64.07,26 75.07,26 v75.82,25.25 76.57,24.5 | v115.07,37.5 115.07,23 110.07,18 102.07,18 102.07,8.5
  Top 0.5: v32.07,25.25 34.32,25.5 42.57,25.5 48.07,20 57.57,20 64.07,26 | 76.57,24.5 76.57,22.5 80.57,18.5 80.57,11 82.07,8.5 102.07,8.5
  Bottom 0.406: R25.1 26.07,37.5 27.57,37 27.57,32 v32.07,25.25 | R24.1 78.62,28.05 v75.82,25.25
  Bottom 0.5: NORBUT.P$3 NORBUT.P$2 115.57,38 | 115.57,38 NORTH.2 | v115.07,37.5 115.57,38
N$18
  Bottom 0.5: RHI_NS.1 103.73,9.64 POT_NS.A
N$19
  Bottom 0.5: Q1.1 99.92,18.55 R17.2
N$20
  Bottom 0.5: Q1.3 107.57,19.5 108.67,20.6 R18.2
N$21
  Bottom 0.406: POT_EW.E 48.11,14.04 50.07,14.5 51.52,14.5 RLO_EW.2
N$22
  Bottom 0.406: RHI_EW.1 40.52,14.55 41.57,14.5 42.57,13.92 POT_EW.A
N$23
  Bottom 0.5: R27.2 84.07,17.5 84.57,18 85.52,18.5 Q2.1
N$25
  Bottom 0.406: RHEW.1 42.67,4.6 43.07,5 45.29,5 EWLED.ARED
N$27
  Bottom 0.61: RLEW.1 D6.C
N$28
  Bottom 0.61: EWLED.CGRN 51.98,3.53 RLEW.2
N$29
  Bottom 0.406: WESBUT.P$4 WESBUT.P$1
  Bottom 0.5: 117.57,1.25 120.57,3.5 SOUBUT.P$3 SOUBUT.P$2 120.57,17 120.07,17.5 SOUTH.1 120.07,18 120.57,19 NORBUT.P$1 | NORTH.1 120.07,39 NORBUT.P$1 | NORBUT.P$1 NORBUT.P$4 120.57,52.5 119.07,54 113.57,54 112.65,53.08 RBUTT.2
  Bottom 0.61: WESBUT.P$1 2.57,18.5 | 67.57,1.25 ESTBUT.P$4 ESTBUT.P$1 67.57,16 68.07,16.5 | 67.57,1.25 4.57,1.25 2.57,3 WESBUT.P$4 | 117.57,1.25 79.57,1.25 76.07,1.23 68.27,1.2 67.57,1.25
  Bottom 1.27: 2.57,18.5 WEST.1 | 68.07,16.5 EAST.1
N$30  (via drill 0.6 pad 1.27, 0.6 pad 1.42)
  Top 0.406: 65.57,9.5 65.57,17.5 67.07,19 73.07,19 74.07,18 74.07,8 76.07,6 | v118.57,22 115.07,18.5 115.07,9.5
  Top 0.5: v11.57,21.5 12.57,21 v34.07,21 38.47,20.5 39.57,20.2 39.57,9.5 65.57,9.5 | 76.07,6 108.07,6 110.57,9.5 115.07,9.5
  Bottom 0.406: NSL.2 28.07,40 28.57,39.5 28.57,32.5 34.07,27 v34.07,21
  Bottom 0.5: NSLED.AGRN 117.57,30.18 117.57,28.5 118.57,28.5 118.84,28.23 NSLED.CRED 118.84,22.23 v118.57,22
  Bottom 0.61: RX2.1 11.07,23 v11.57,21.5
N$37
  Bottom 0.305: LED3.A 40.02,36.2
  Bottom 0.61: 40.02,36.2 38.27,36.2 R36.1
  Bottom 0.813: LED3.A 40.57,33.38 QE.C
N$39  (via drill 0.6, 0.6 pad 1.27)
  Top 0.5: v25.57,49 25.57,35.5 v20.07,32
  Bottom 0.406: R44.1 26.17,47.5 R45.1 25.17,48.6 v25.57,49 | v20.07,32 20.07,26 21.57,25 21.57,14.5 7.57,14.5
  Bottom 0.61: WESBUT.P$3 7.57,14.5 WESBUT.P$2
  Bottom 1.27: 7.57,14.5 WEST.2
N$41
  Bottom 0.5: D9.A 114.57,33.45 RHINS.2
N$42
  Bottom 0.5: RHINS.1 118.57,34 119.07,33.5 119.07,30.68 NSLED.ARED
N$43
  Bottom 0.5: D8.C 112.57,22.95 RLNS.1
N$44
  Bottom 0.5: RLNS.2 115.62,23.55 117.57,25.5 117.57,26.18 NSLED.CGRN
N$54  (via drill 0.6, 0.6 pad 1.78)
  Top 0.5: 56.57,44.5 v56.57,42.5 | 56.57,44.5 v56.57,46.5 | v38.07,50 40.57,48 45.57,44.5 56.57,44.5
  Bottom 0.305: FET4.2 55.44,46.13 v56.57,46.5
  Bottom 0.406: FET4.4 54.41,42.5 v56.57,42.5 | R41.1 35.17,47.5 R46.2 36.47,48.4
  Bottom 0.61: 36.47,48.4 v38.07,50
N$55  (via drill 0.6, 0.6 pad 1.78)
  Top 0.5: 56.57,36 v56.57,34 | 56.57,36 v56.57,38 | v34.27,39.8 37.07,39.5 40.57,36 56.57,36
  Bottom 0.305: v56.57,38 56.08,38.06 55.44,38.13 | v34.27,39.8 35.07,40
  Bottom 0.406: FET3.4 54.91,34 v56.57,34 | v34.27,39.8 35.77,40.2
  Bottom 0.5: FET3.2 56,38.13 56.08,38.06
  Bottom 0.61: 35.07,40 R31.1 | v34.27,39.8 34.57,38.4 R36.2
N$56
  Bottom 0.61: LED3.C 40.17,40.5 R32.1
NOREND
  Top 0.406: X1.N 76.07,33.5 79.57,25.5 NOREND.1
  Bottom 0.5: QN.B 77.12,18 R23.1 78.47,22.5 NOREND.1 79.07,24 R24.2
RAIN
  Top 0.254: 65.87,47.2 69.37,47.2
  Top 0.406: 64.57,48.5 65.87,47.2 | 69.37,47.2 X1.L
  Top 0.5: RAIN.1 23.57,51.5 25.07,53 59.57,53 60.07,52.5 64.57,48.5
  Bottom 0.406: MIC.5 11.87,48.49 11.87,49.9 12.19,50.12 JP6.7 21.45,51.5 RAIN.1
RB4
  Bottom 0.305: MIC.3 9.3,45.77 10.07,45 16.07,45
  Bottom 0.406: 16.07,45 17.07,45 18.07,43.4 JP6.4 EWL.1
RB5
  Bottom 0.406: MIC.2 8.07,46.82 8.07,45 9.07,44 16.07,44 16.61,39.96 JP6.3 22.93,39.96 NSL.1
RC0  (1 unrouted)
  Bottom 0.305: MIC.10 11.84,36.27 7.07,34.8 1.8,34.8
RC1
  Bottom 0.305: R15.2 20.69,35 20.57,34.88
  Bottom 0.406: MIC.9 13.11,35.96 14.07,34.8 19.95,34.8 JP6.1 20.57,34.88 20.9,34.88
RC2
  Bottom 0.305: R25.2 20.15,37.5 JP6.2
  Bottom 0.406: MIC.8 14.38,38.49 15.17,38 18.15,38 JP6.2
RC3  (1 unrouted)
  Bottom 0.406: MIC.7 17.21,46.86 18.57,46 19.03,45.5 JP6.5 22.93,45.04 R35.2
RC4  (1 unrouted)
  Bottom 0.406: MIC.6 13.07,46.9 13.07,49 17.07,49 17.99,48.08 JP6.6 22.89,47.58 R45.2
SOU_END
  Top 0.406: SOUTEND.1 94.57,24
  Top 0.5: 94.57,24 100.07,29.5 100.07,49.5 99.57,50 85.07,50 83.57,48.5 83.57,43.5 82.07,42 X1.R
  Bottom 0.5: R13.1 96.02,11.15 QS.B 97.47,12.9 97.57,14 97.57,17 | R14.2 110.02,15.55 108.57,17 97.57,17 | 97.57,17 96.57,17 95.07,18.5 SOUTEND.1
V+  (via drill 0.6, 0.6 pad 1.42, 0.8 pad 1.78)  (1 unrouted)
  Top 0.5: v37.57,34.5 36.07,37.5 | IC1.GND 49.07,25.5 49.57,26
  Bottom 0.305: MIC.1 5.94,47.54 2.61,47.54 2.07,47 2.04,47
  Bottom 0.406: 35.18,44.11 QW.E 35.07,43.84 | R43.2 33.66,44.11 | D1.C 47.34,9 C1.1 43.47,9.2 41.27,11.4 40.12,11.4 RHI_EW.2 | 56.57,23 56.57,23.18 P4C1.+ | D7.C 30.97,4.6 | v37.57,34.5 37.8,34.27 | 71.07,24 v70.07,24 | 91.07,36.5 91.43,36.87 91.07,37 | 71.07,30 71.57,30.5 | FET2.3 92.43,44.87 91.07,44 | 90.07,30.5 90.57,30.5 | V+INPUT.1 70.57,31 | 84.07,30.5 v85.07,30.5 84.57,30 84.07,30.5
  Bottom 0.5: D9.C 114.57,26.5 114.07,26 113.07,26 | 113.07,26 v112.57,26 | 91.43,36.87 FET1.3 | R23.2 79.52,18.5 QN.E 79.52,18.45 81.07,20 84.57,20 85.07,20.5 v85.07,30.5 | QS.E 93.62,10.65 R13.2 | 88.01,6.06 RHI_NS.2 | 88.01,6.06 79.57,6 78.57,9 v78.07,9 | 91.07,6 88.07,6.12 88.01,6.06 | R16.1 112.87,26.2 113.07,26 | FET4.8 50.48,47.41 50.57,47.5 50.57,46 48.46,46 FET4.7 | FET3.8 50.48,39.41 50.57,39.5 50.57,38 50.07,38 | 50.07,38 48.57,38 | v50.07,34 50.07,38 | 40.12,11.4 31.97,11.4 v28.07,7.5
  Bottom 0.61: 33.66,44.11 35.18,44.11 | 37.8,34.27 QE.E | v37.57,34.5 37.07,34.49 R33.1 | 30.97,4.6 v28.07,7.5 | 35.07,43.84 v35.07,45.5
  Bottom 1.016: 56.57,23 58.07,21.5 70.57,21.5 71.07,22 71.07,24 71.07,30 V+INPUT.1 X1.H
  Bottom 1.27: 91.07,36.5 91.07,31.5 90.07,30.5 v85.07,30.5 | 71.57,30.5 84.07,30.5 | 91.07,37 91.07,44 | v50.07,34 50.07,31 70.57,31
  pour Bottom (isolate 0.61): 48.07,48 51.07,48 52.07,47 52.07,34 53.07,33 49.07,33 49.07,46 48.07,47.5
  pour Top (isolate 0.5, rank 2): 2.57,54 70.57,54 78.57,50.5 79.07,32.5 116.07,32.5 116.07,3 2.57,3
  pour Bottom (isolate 0.5): 76.57,10.5 79.57,10.5 79.57,8.5 81.57,6.5 90.57,6.5 91.57,7.5 91.57,8 92.57,9 96.57,9 98.07,7.5 101.57,7.5 102.07,7 102.07,4 101.07,3 78.57,3 76.57,5 76.57,10
V-
  Bottom 0.305: R31.2 38.27,38.8 39.57,37.5 41.57,37.5
  Bottom 0.406: IC1.IN 51.57,23.5 52.57,24 52.57,24.47 P4C1.- | 106.17,50.6 106.07,50.5 106.07,39.5 106.57,39
  Bottom 0.5: RBUTT.1 110.35,50.88 R22.2 106.17,50.6 | 106.57,39 R12X.2 | 41.57,37.5 45.57,37.5 46.07,37 48.19,37 FET3.6 | FET4.6 46.94,44.87 46.57,44.5 46.57,43.5 48.23,43.5 FET4.5
  pour Bottom (isolate 1, rank 4): 33.57,54 109.07,54 109.07,24 40.57,24 40.57,49.5 33.57,49.5
VSS  (via drill 0.6 pad 1.42)  (1 unrouted)
  Top 0.406: 61.57,3 v63.57,4.5
  Top 0.5: v63.57,4.5 65.57,2.5 112.07,2.5 v112.07,7 | 61.57,3 21.57,3 19.57,5 v19.57,16.5
  Bottom 0.305: MIC.14 6.07,43.33 6.07,44 5.07,45 1.64,45
  Bottom 0.406: JP3.3 2.53,45 0.57,45 0.07,44.5 0.07,32 2.34,29.73 2.34,25.87 C2.2 2.34,24.92 3.57,23 7.57,23 10.57,18.5 15.57,18.5 RLONS.1 18.63,19 v19.57,16.5 | 51.57,9.17 RLO_EW.1 | 51.57,9.17 D1.A | 51.57,7 51.57,9.17 | 40.57,8.6 C1.2 | 59.57,7 59.07,7 C3.2 | 61.07,4.7 D6.A 60.97,4.4 v63.57,4.5 | 49.07,21.5 IC1.OUT | 53.07,7 53.57,7.5
  Bottom 0.5: v112.07,7 111.57,8 111.57,17.3 D8.A
  Bottom 0.61: 40.57,8.6 40.57,7 51.57,7 53.07,7 59.07,7 | 59.57,7 61.07,6.5 61.07,4.7 | 49.07,21.5 53.57,17 53.57,7.5 | IC1.OUT 46.46,22.23 R2.2
WESTEND
  Top 0.254: 62.07,42.5 arc71 66.07,43.5
  Top 0.406: 66.07,43.5 X1.F
  Top 0.5: WENDS.1 34.07,48 41.57,40.8 57.57,40.8 62.07,42.5
  Bottom 0.406: R44.2 28.97,46.2
  pour Bottom (isolate 0.61): 32.57,48.5 31.07,45 31.57,42.5 35.57,42.5 35.57,41 35.17,40.9 30.67,40.9 30.07,41 30.07,44 28.57,45.5 28.57,47
WIND  (1 unrouted)
  Top 0.406: 61.07,54 62.57,52.5 X1.G
  Top 0.5: WIND.1 4.07,54 61.07,54
  Bottom 0.305: MIC.4 10.57,49.5 10.49,50.08 1.64,50.08
  Bottom 0.406: JP3.1 WIND.1

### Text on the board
Top: MICHAEL5.net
